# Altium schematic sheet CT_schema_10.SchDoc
size 277 x 170 mm
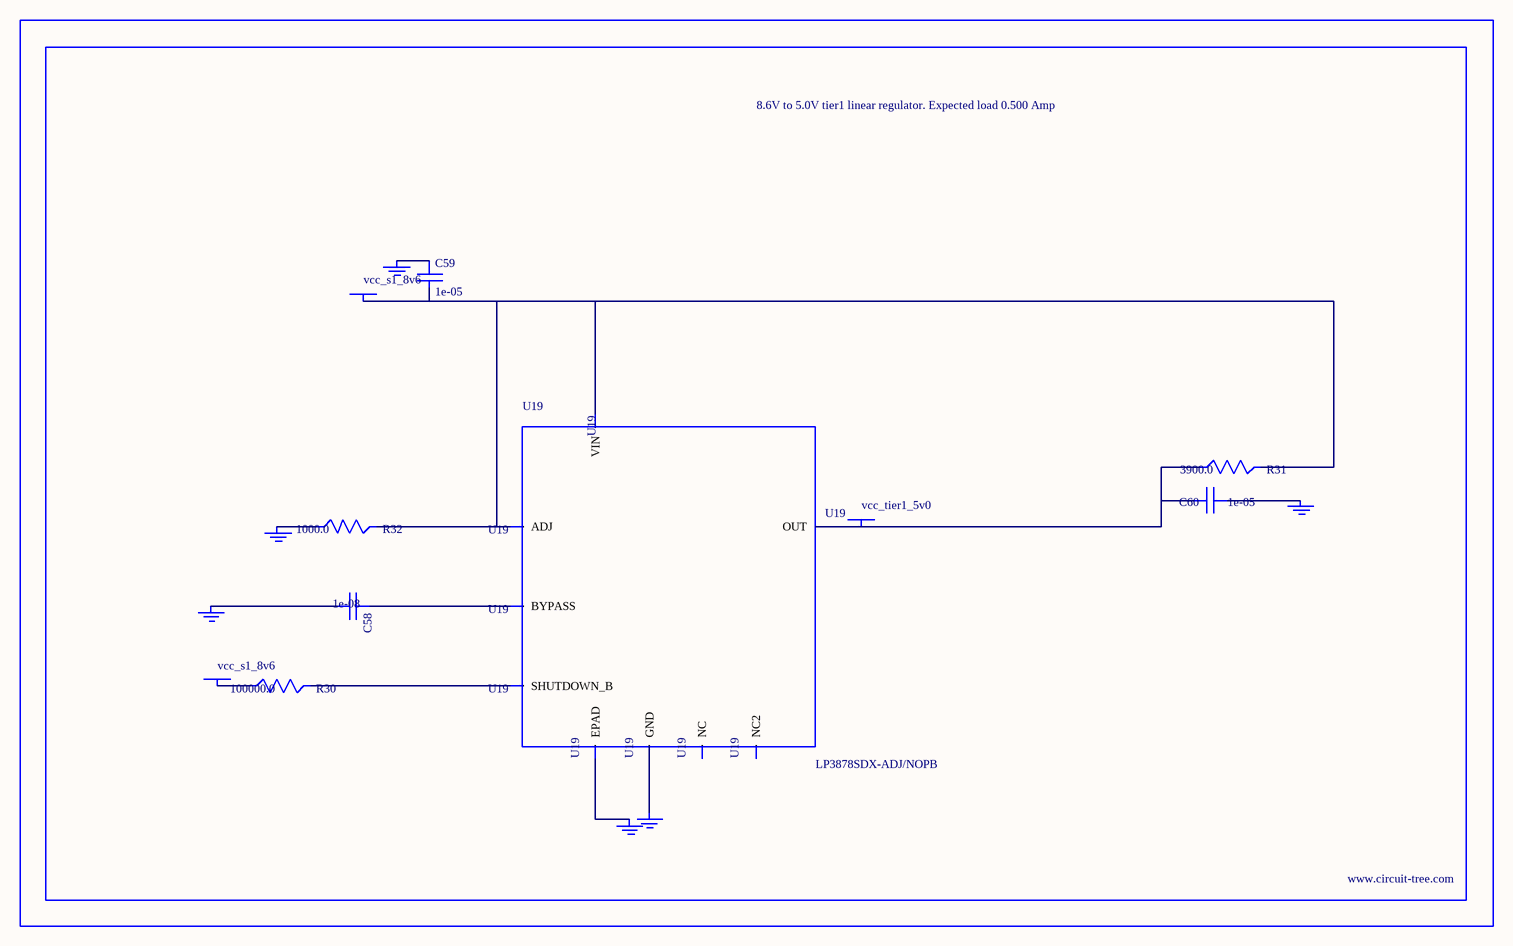
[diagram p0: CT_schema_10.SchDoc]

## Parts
BORDER9  (no value)
C58  1e-08  [C0402]
C59  1e-05  [C1206]
C60  1e-05  [C1210]
GND_INSTANCE_9_0  (no value)
GND_INSTANCE_9_1  (no value)
GND_INSTANCE_9_2  (no value)
GND_INSTANCE_9_3  (no value)
GND_INSTANCE_9_4  (no value)
GND_INSTANCE_9_5  (no value)
POWER_INSTANCE_9_0  vcc_s1_8v6
POWER_INSTANCE_9_1  vcc_s1_8v6
POWER_INSTANCE_9_2  vcc_tier1_5v0
R30  100000.0  [R0603]
R31  3900.0  [R0603]
R32  1000.0  [R0603]
U19  LP3878SDX-ADJ/NOPB  [WSON-8]

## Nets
NetC58_1: C58.1 U19.1(BYPASS)
NetC58_2: C58.2 GND_INSTANCE_9_0.0(GND)
NetC59_1: C59.1 GND_INSTANCE_9_1.0(GND)
NetC59_2: C59.2 POWER_INSTANCE_9_0.0(PWR) R31.2 R32.2 U19.4(VIN) U19.6(ADJ)
NetC60_1: C60.1 GND_INSTANCE_9_2.0(GND)
NetC60_2: C60.2 POWER_INSTANCE_9_2.0(PWR) R31.1 U19.5(OUT)
NetGND_INSTANCE_9_3_0: GND_INSTANCE_9_3.0(GND) R32.1
NetGND_INSTANCE_9_4_0: GND_INSTANCE_9_4.0(GND) U19.PAD(EPAD)
NetGND_INSTANCE_9_5_0: GND_INSTANCE_9_5.0(GND) U19.3(GND)
NetPOWER_INSTANCE_9_1_0: POWER_INSTANCE_9_1.0(PWR) R30.1
NetR30_2: R30.2 U19.8(SHUTDOWN_B)

Not connected (* = marked no-connect by the designer): U19 2(NC) 7(NC2)

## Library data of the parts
BORDER9 = BORDER_PAGE9
C58 = C0402C103K3RAC
C59 = C1206C106K3RACTU
C60 = GRM32DR61E106MA12L
GND_INSTANCE_9_0-GND_INSTANCE_9_5 = GND
POWER_INSTANCE_9_0-POWER_INSTANCE_9_2 = PWR
R30 = RC0603JR-07100KL
R31 = RC0603JR-073K9L
R32 = RC0603JR-071KL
